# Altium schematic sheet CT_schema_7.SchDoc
size 266 x 267 mm
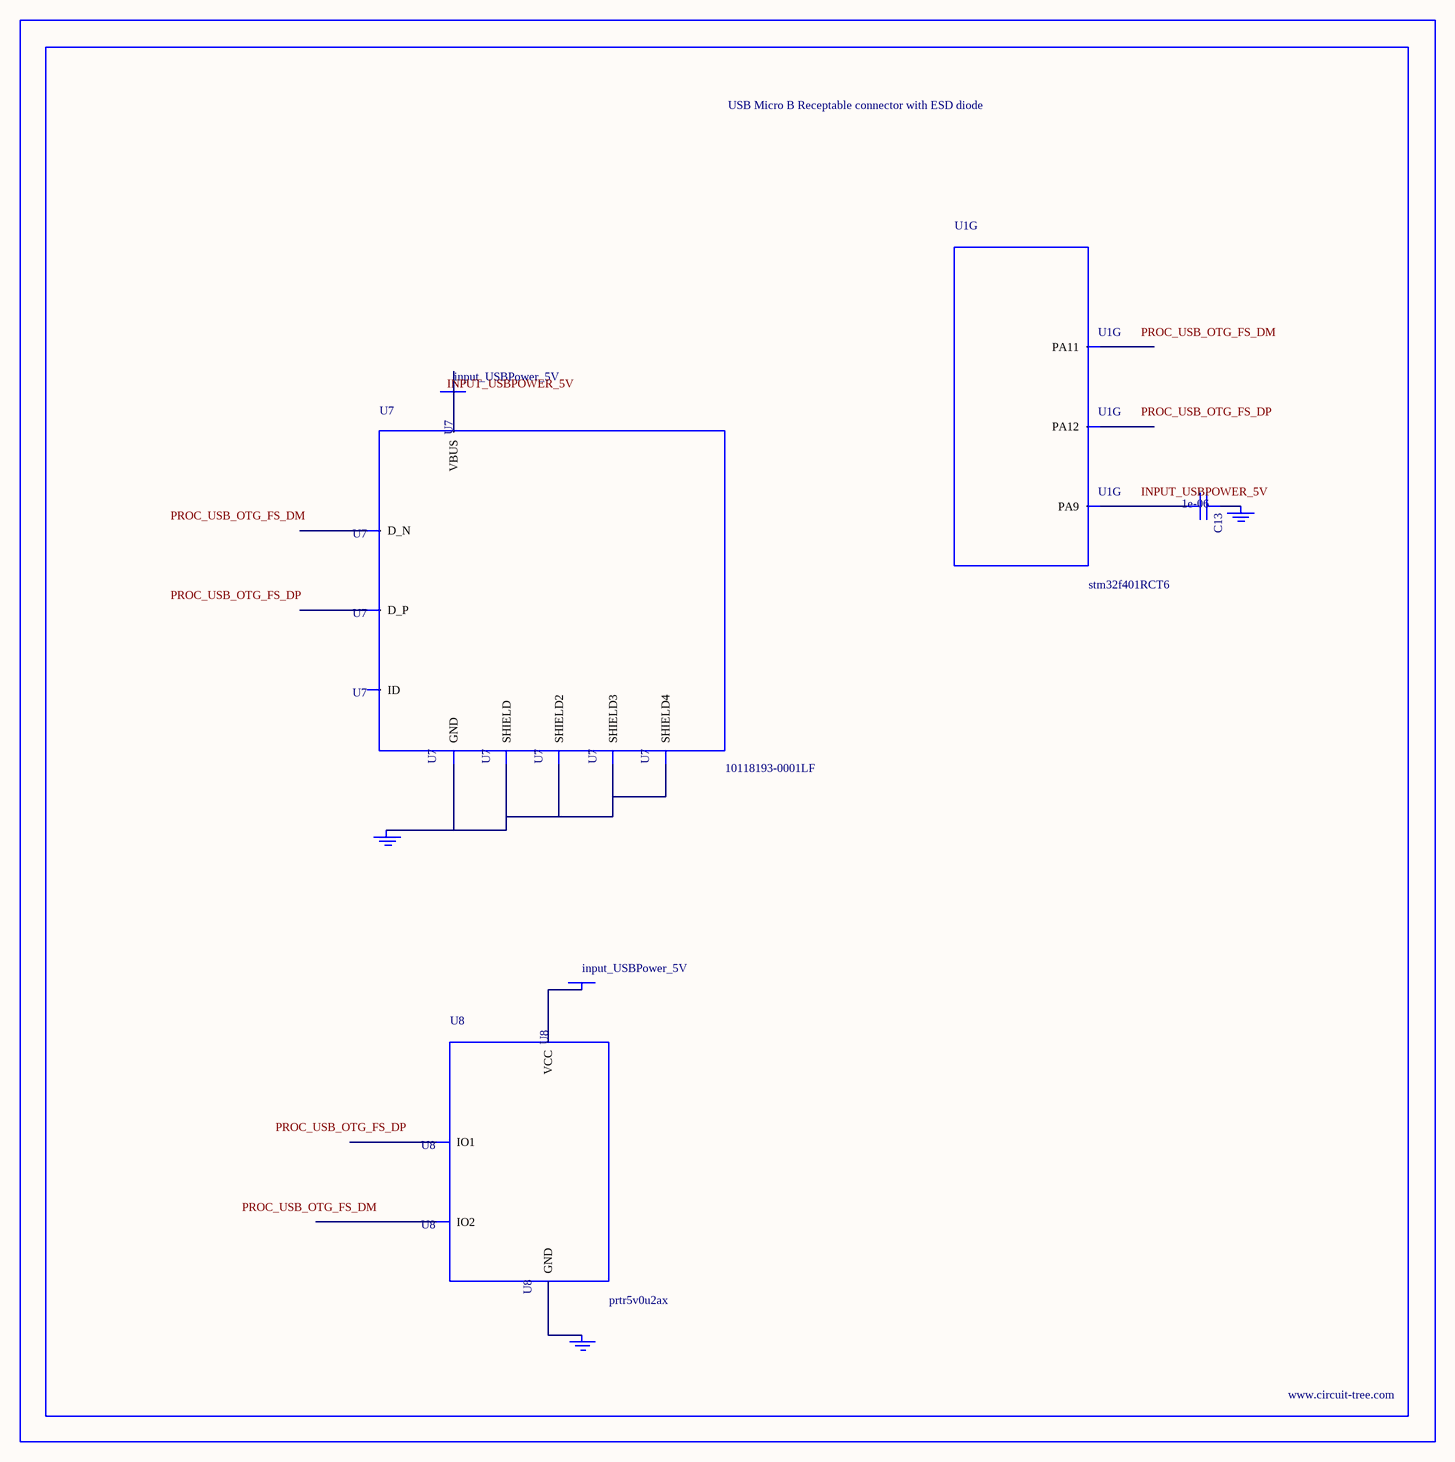
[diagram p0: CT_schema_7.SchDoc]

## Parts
BORDER6  (no value)
C13  1e-06  [C0603]
GND_INSTANCE_6_0  (no value)
GND_INSTANCE_6_1  (no value)
GND_INSTANCE_6_2  (no value)
POWER_INSTANCE_6_0  input_USBPower_5V
POWER_INSTANCE_6_1  input_USBPower_5V
U1  stm32f401RCT6  [LQFP64]  (part G of 9)
U7  10118193-0001LF  [FCI_10118193-0001LF]
U8  prtr5v0u2ax  [SOT143B]

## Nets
NetC13_1: C13.1 GND_INSTANCE_6_1.0(GND)
NetC13_2: C13.2 U1.42(PA9)
NetGND_INSTANCE_6_0_0: GND_INSTANCE_6_0.0(GND) U7.5(GND) U7.6(SHIELD) U7.7(SHIELD2) U7.8(SHIELD3) U7.9(SHIELD4)
NetGND_INSTANCE_6_2_0: GND_INSTANCE_6_2.0(GND) U8.1(GND)
NetPOWER_INSTANCE_6_0_0: POWER_INSTANCE_6_0.0(PWR) U7.1(VBUS)
NetPOWER_INSTANCE_6_1_0: POWER_INSTANCE_6_1.0(PWR) U8.4(VCC)

Not connected (* = marked no-connect by the designer): U1 44(PA11) 45(PA12); U7 2(D_N) 3(D_P) 4(ID); U8 2(IO1) 3(IO2)

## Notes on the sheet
- Labels drawn without touching a wire or pin: INPUT_USBPOWER_5V, PROC_USB_OTG_FS_DM, PROC_USB_OTG_FS_DP

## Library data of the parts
BORDER6 = BORDER_PAGE6
C13 = C0603C105K3RACTU
GND_INSTANCE_6_0-GND_INSTANCE_6_2 = GND
POWER_INSTANCE_6_0 POWER_INSTANCE_6_1 = PWR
